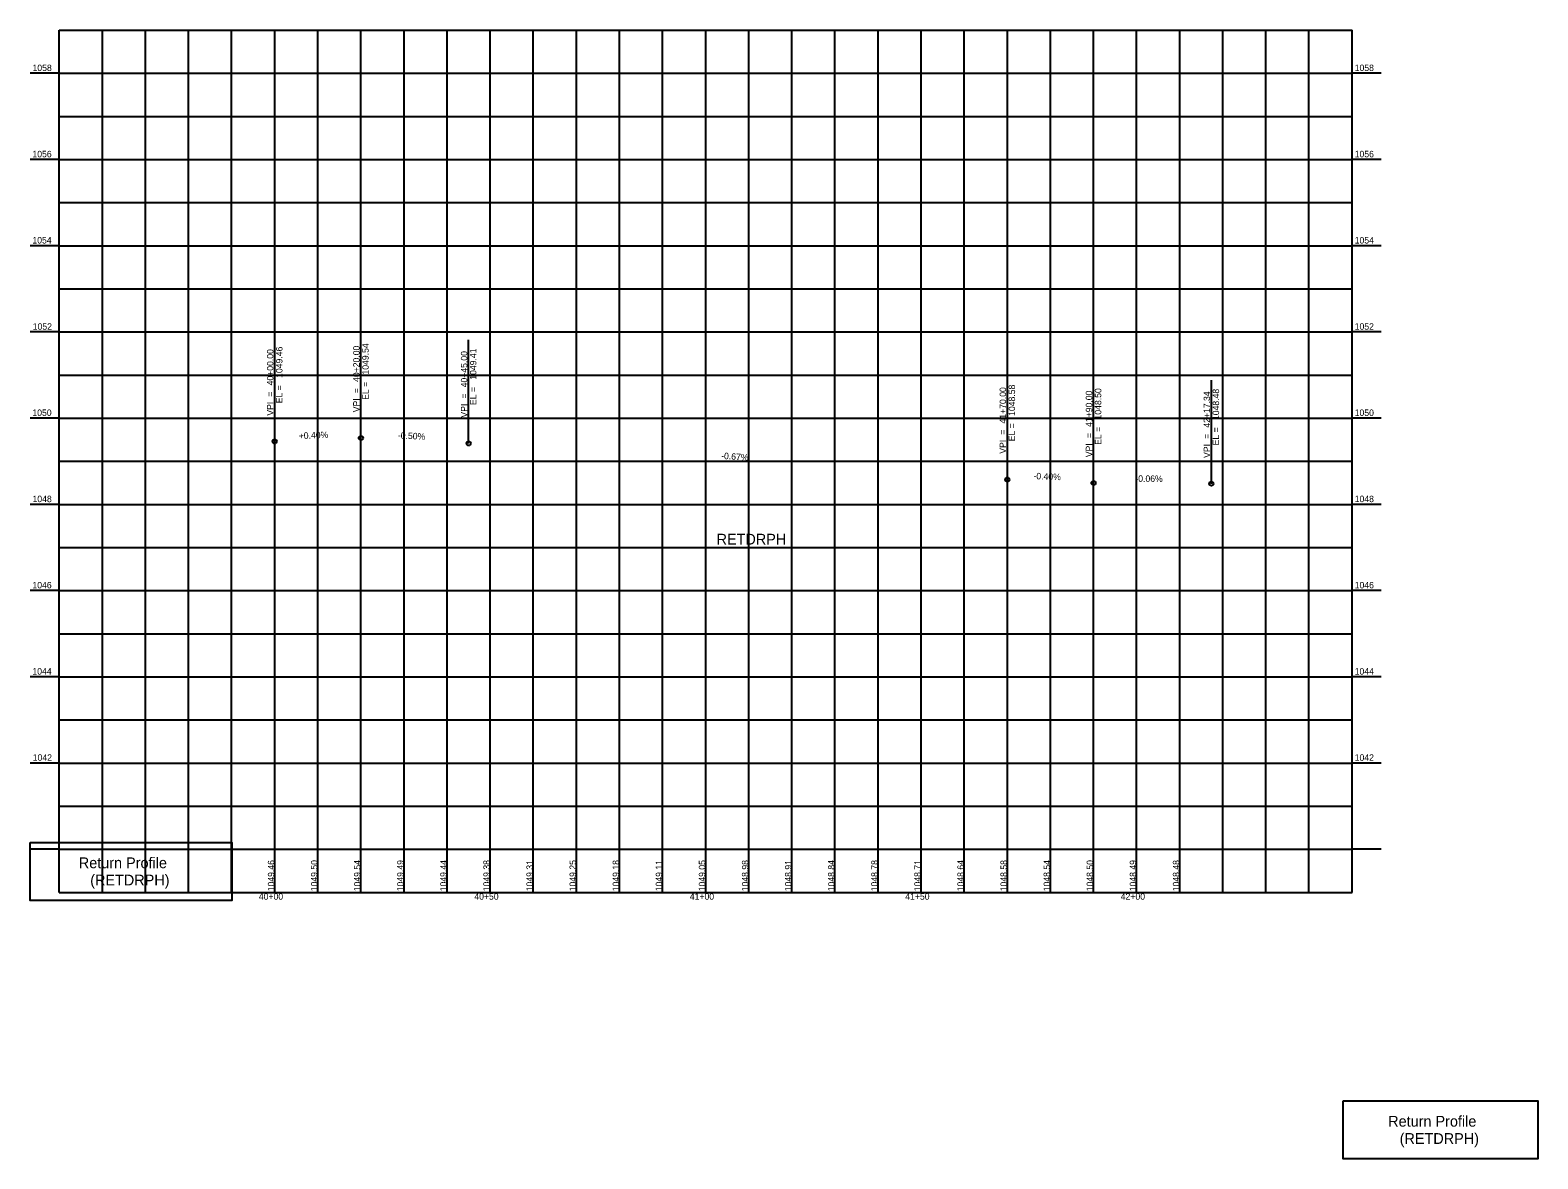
# Model space of a CAD drawing. Extents: x -57 to 293, y 977 to 1239.
import ezdxf

# ---------------------------------------------------------------- set-up
doc = ezdxf.new("R2010")
doc.units = 0
for name, color, linetype in [('_CIVIL_CONSTRUCTION', 7, 'Continuous'), ('Default', 7, 'Continuous'), ('Draft_DNC', 7, 'Continuous'), ('ImpactArea', 7, 'Continuous'), ('Point', 7, 'Continuous'), ('SheetText', 7, 'Continuous'), ('TextNonPlot', 7, 'Continuous'), ('TL_GroundIntercept', 7, 'Continuous')]:
    doc.layers.add(name, color=color, linetype=linetype)

msp = doc.modelspace()

# ---------------------------------------------------------------- linework, layer by layer
at = {"layer": '_CIVIL_CONSTRUCTION'}
for points in [[(-56.75, 1050.56), (-9.95, 1050.56), (-9.95, 1037.14), (-56.75, 1037.14)], [(247.89, 990.61), (293.1, 990.61), (293.1, 977.18), (247.89, 977.18)]]:
    msp.add_lwpolyline(points, close=True, dxfattribs=at)
at = {"layer": 'Draft_DNC'}
for p, q in [((-50, 1039), (-50, 1239)), ((0, 1039), (0, 1239)), ((50, 1039), (50, 1239)), ((100, 1039), (100, 1239)), ((150, 1039), (150, 1239)), ((200, 1039), (200, 1239)), ((-50, 1229), (-56.75, 1229)), ((-50, 1229), (250, 1229)), ((256.75, 1229), (250, 1229)), ((-50, 1209), (-56.75, 1209)), ((-50, 1209), (250, 1209)), ((256.75, 1209), (250, 1209)), ((-50, 1189), (-56.75, 1189)), ((-50, 1189), (250, 1189)), ((256.75, 1189), (250, 1189)), ((-50, 1169), (-56.75, 1169)), ((-50, 1169), (250, 1169)), ((256.75, 1169), (250, 1169)), ((-50, 1149), (-56.75, 1149)), ((-50, 1149), (250, 1149)), ((256.75, 1149), (250, 1149)), ((-50, 1129), (-56.75, 1129)), ((-50, 1129), (250, 1129)), ((256.75, 1129), (250, 1129)), ((-50, 1109), (-56.75, 1109)), ((-50, 1109), (250, 1109)), ((256.75, 1109), (250, 1109)), ((-50, 1089), (-56.75, 1089)), ((-50, 1089), (250, 1089)), ((256.75, 1089), (250, 1089)), ((-50, 1069), (-56.75, 1069)), ((-50, 1069), (250, 1069)), ((256.75, 1069), (250, 1069)), ((-50, 1049), (-56.75, 1049)), ((-50, 1049), (250, 1049)), ((256.75, 1049), (250, 1049))]:
    msp.add_line(p, q, dxfattribs=at)
at = {"layer": 'Point'}
for p, q in [((-50, 1239), (250, 1239)), ((-50, 1039), (-50, 1239)), ((250, 1039), (250, 1239)), ((-50, 1039), (250, 1039))]:
    msp.add_line(p, q, dxfattribs=at)
at = {"layer": 'TextNonPlot'}
for p, q in [((-40, 1039), (-40, 1239)), ((-30, 1039), (-30, 1239)), ((-20, 1039), (-20, 1239)), ((-10, 1039), (-10, 1239)), ((10, 1039), (10, 1239)), ((20, 1039), (20, 1239)), ((30, 1039), (30, 1239)), ((40, 1039), (40, 1239)), ((60, 1039), (60, 1239)), ((70, 1039), (70, 1239)), ((80, 1039), (80, 1239)), ((90, 1039), (90, 1239)), ((110, 1039), (110, 1239)), ((120, 1039), (120, 1239)), ((130, 1039), (130, 1239)), ((140, 1039), (140, 1239)), ((160, 1039), (160, 1239)), ((170, 1039), (170, 1239)), ((180, 1039), (180, 1239)), ((190, 1039), (190, 1239)), ((210, 1039), (210, 1239)), ((220, 1039), (220, 1239)), ((230, 1039), (230, 1239)), ((240, 1039), (240, 1239)), ((-50, 1219), (250, 1219)), ((-50, 1199), (250, 1199)), ((-50, 1179), (250, 1179)), ((-50, 1159), (250, 1159)), ((-50, 1139), (250, 1139)), ((-50, 1119), (250, 1119)), ((-50, 1099), (250, 1099)), ((-50, 1079), (250, 1079)), ((-50, 1059), (250, 1059))]:
    msp.add_line(p, q, dxfattribs=at)
at = {"layer": 'TL_GroundIntercept'}
for p, q in [((0, 1143.59), (0, 1167.59)), ((20, 1144.39), (20, 1168.39)), ((45, 1143.14), (45, 1167.14)), ((170, 1134.76), (170, 1158.76)), ((190, 1133.96), (190, 1157.96)), ((217.34, 1133.8), (217.34, 1157.8))]:
    msp.add_line(p, q, dxfattribs=at)
for centre in [(0, 1143.59), (20, 1144.39), (45, 1143.14), (170, 1134.76), (190, 1133.96), (217.34, 1133.8)]:
    msp.add_circle(centre, 0.486, dxfattribs=at)

# ---------------------------------------------------------------- texts
at = {"layer": 'Default'}
msp.add_text('RETDRPH', height=2.5, dxfattribs=at).set_placement((102.54, 1119.67))
at = {"layer": 'ImpactArea'}
for s, rotation, p in [('1049.46', 90, (1.8, 1158.33)), ('40+20.00', 90, (19.7, 1157.39)), ('1049.54', 90, (21.8, 1159.11)), ('1049.41', 90, (46.8, 1157.91)), ('40+00.00', 90, (-0.3, 1156.59)), ('40+45.00', 90, (44.7, 1156.14)), (' = ', 90, (-0.3, 1153.43)), ('EL = ', 90, (1.8, 1152.45)), (' = ', 90, (19.7, 1154.23)), ('EL = ', 90, (21.8, 1153.24)), (' = ', 90, (44.7, 1152.98)), ('EL = ', 90, (46.8, 1152.03)), ('41+70.00', 90, (169.7, 1147.76)), ('1048.58', 90, (171.8, 1149.52)), ('41+90.00', 90, (189.7, 1146.96)), ('1048.50', 90, (191.8, 1148.69)), ('42+17.34', 90, (217.04, 1146.79)), ('1048.48', 90, (219.14, 1148.55)), ('VPI', 90, (-0.3, 1149.57)), ('VPI', 90, (19.7, 1150.37)), ('VPI', 90, (44.7, 1149.12)), ('EL = ', 90, (171.8, 1143.64)), ('+0.40%', 2.2906, (5.6, 1144.14)), ('-0.50%', 357.1376, (28.54, 1144.29)), (' = ', 90, (169.7, 1144.61)), (' = ', 90, (189.7, 1143.81)), ('EL = ', 90, (191.8, 1142.81)), (' = ', 90, (217.04, 1143.64)), ('EL = ', 90, (219.14, 1142.68)), ('-0.67%', 356.1669, (103.55, 1139.55)), ('VPI', 90, (169.7, 1140.74)), ('VPI', 90, (189.7, 1139.94)), ('VPI', 90, (217.04, 1139.77)), ('-0.40%', 357.7094, (176.04, 1134.85)), ('-0.06%', 359.6475, (199.7, 1134.23)), ('1049.46', 90, (-0.09, 1039.24)), ('1049.50', 90, (9.91, 1039.24)), ('1049.54', 90, (19.91, 1039.24)), ('1049.49', 90, (29.91, 1039.24)), ('1049.44', 90, (39.91, 1039.24)), ('1049.38', 90, (49.91, 1039.24)), ('1049.31', 90, (59.91, 1039.24)), ('1049.25', 90, (69.91, 1039.24)), ('1049.18', 90, (79.91, 1039.24)), ('1049.11', 90, (89.91, 1039.24)), ('1049.05', 90, (99.91, 1039.24)), ('1048.98', 90, (109.91, 1039.24)), ('1048.91', 90, (119.91, 1039.24)), ('1048.84', 90, (129.91, 1039.24)), ('1048.78', 90, (139.91, 1039.24)), ('1048.71', 90, (149.91, 1039.24)), ('1048.64', 90, (159.91, 1039.24)), ('1048.58', 90, (169.91, 1039.24)), ('1048.54', 90, (179.91, 1039.24)), ('1048.50', 90, (189.91, 1039.24)), ('1048.49', 90, (199.91, 1039.24)), ('1048.48', 90, (209.91, 1039.24))]:
    msp.add_text(s, height=1.5, rotation=rotation, dxfattribs=at).set_placement(p)
at = {"layer": 'SheetText'}
for s, p in [('Return Profile  ', (-45.46, 1044.6)), ('(RETDRPH)', (-42.81, 1040.6)), ('Return Profile  ', (258.38, 984.65)), ('(RETDRPH)', (261.04, 980.64))]:
    msp.add_text(s, height=2.502, rotation=360, dxfattribs=at).set_placement(p)
at = {"layer": 'TL_GroundIntercept'}
for s, p in [('1058', (-56.2, 1229.51)), ('1058', (250.6, 1229.51)), ('1056', (-56.22, 1209.51)), ('1056', (250.6, 1209.51)), ('1054', (-56.23, 1189.51)), ('1054', (250.6, 1189.51)), ('1052', (-56.15, 1169.51)), ('1052', (250.6, 1169.51)), ('1050', (-56.23, 1149.51)), ('1050', (250.6, 1149.51)), ('1048', (-56.2, 1129.51)), ('1048', (250.6, 1129.51)), ('1046', (-56.22, 1109.51)), ('1046', (250.6, 1109.51)), ('1044', (-56.23, 1089.51)), ('1044', (250.6, 1089.51)), ('1042', (-56.15, 1069.51)), ('1042', (250.6, 1069.51)), ('40+00', (-3.68, 1037.29)), ('40+50', (46.32, 1037.29)), ('41+00', (96.32, 1037.29)), ('41+50', (146.32, 1037.29)), ('42+00', (196.32, 1037.29))]:
    msp.add_text(s, height=1.5, dxfattribs=at).set_placement(p)

doc.saveas('drawing.dxf')
